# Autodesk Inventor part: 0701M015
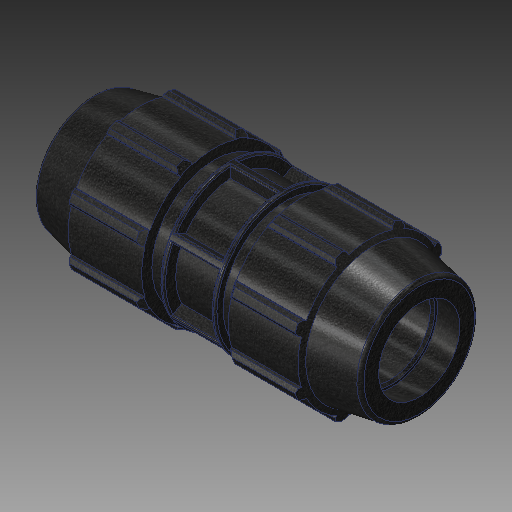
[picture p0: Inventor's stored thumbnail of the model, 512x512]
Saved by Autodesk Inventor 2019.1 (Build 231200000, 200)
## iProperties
Created: 2017-02
Part Number: 0701M015
Material: PVC-Piping
Description: PLASSON COUPLER 1 1/2'' - 50mm
Document SubType Name: Modeling
Designer: KIM
Mass: 92.6774 g
Surface Area: 199.44 cm^2
Volume: 66.1981 cm^3
Density: 1.4 g/cm^3
Appearance: PTFE
Author: KIM
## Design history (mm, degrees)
derived "0701M.ipt"
feature "Solid1::0701M.ipt"
tag "TaggingFeature1"
body "Solid1"
other parameters: "d4" = 16.74283, "d5" = 28.702, "d7" = 96.012, "d8" = 72.009, "d9" = 28.702, "d11" = 2.8702, "d12" = 76.8096, "d13" = 120 deg, "d14" = 72.15, "d15" = 10 deg, "d16" = 86.4108, "d18" = 2.405, "d19" = 35 deg, "d20" = 17.5 deg, "d21" = 89.29116, "d23" = 0, "d25" = 360 deg, "d27" = 1.92024, "d33" = 0.962, "d34" = 4.8006, "d36" = 0, "d37" = 0.962, "d38" = 0.962, "d40" = 360 deg, "d42" = 44.20108, "d43" = 2.88036, "d46" = 1.443, "d50" = 38.48, "d51" = 98.044, "d53" = 2.8702, "d54" = 44.20108, "d55" = 120 deg, "d56" = 12 deg, "d57" = 16.74283, "d58" = 200.914, "d59" = 28.702, "d63" = 28.702, "d68" = 0, "d69" = 0.962, "d70" = 2.405, "d72" = 0, "d73" = 2.88036, "d77" = 98.044, "d78" = 48.1, "d_" = 48.1, "E_" = 96.012, "H_" = 200.914, "l_" = 98.044
